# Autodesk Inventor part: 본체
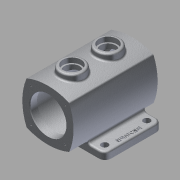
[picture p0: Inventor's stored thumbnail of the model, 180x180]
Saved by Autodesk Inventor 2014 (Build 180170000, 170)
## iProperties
Created: 2013-02
Part Number: 본체
Document SubType Name: Modeling
Designer: 한국산업디자인학원[gmhk.co.kr]
Density: 2.71 g/cm^3
Material: 알루미늄 6061
Mass: 1212.6 g
Surface Area: 1019.31 cm^2
Volume: 447.452 cm^3
Appearance: _시험_알루미늄 표면거칠기
Author: 한국산업디자인학원[gmhk.co.kr]
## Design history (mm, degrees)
sketch "스케치1"
  geometry: L1 (-65, 55)-(65, 55); L2 (65, 55)-(65, -40); L3 (65, -40)-(-65, -40); L4 (-65, -40)-(-65, 55); 2 further points
  constraints: 8 end point, 2 parallel, 1 horizontal, 1 midpoint, 1 perpendicular, 1 vertical alignment
  dimensions: "d0" = 130 distance of L2.end L3.end; "d1" = 95 distance of L1.end L2.end; "d47" = 40 distance from line of L3 point (0, 0)
extrude "돌출1" new body sketch "스케치1" distance "d2" = 12; taper "d3" = 0 deg
sketch "스케치2"
  geometry: L1 (-35.355, 85.355)-(35.355, 85.355); L2 (35.355, 85.355)-(35.355, 14.645); L3 (35.355, 14.645)-(-35.355, 14.645); L4 (-35.355, 14.645)-(-35.355, 85.355); L5 (35.355, 85.355)-(-35.355, 14.645); L6 (65, 0)-(-65, 0) reference; A1 r 91.05 centre (0, 1.45) between (35.355, 85.355) and (-35.355, 85.355); A2 r 91.05 centre (-48.55, 50) between (35.355, 14.645) and (35.355, 85.355); A3 r 91.05 centre (0, 98.55) between (-35.355, 14.645) and (35.355, 14.645); A4 r 91.05 centre (48.55, 50) between (-35.355, 85.355) and (-35.355, 14.645); 3 further points
  constraints: 10 end point, 8 point on circle, 4 centre point, 3 equal radius, 2 midpoint, 2 parallel, 2 perpendicular, 1 horizontal, 1 vertical alignment
  dimensions: "d4" = 50 distance from line of point (0, 50) L6; "d5" = 50 distance of L1.start point (0, 50); "d6" = 85 dimension on A2 A4
extrude "돌출2" join sketch "스케치2" stored distance "d7" = 140; taper "d8" = 0 deg
sketch "스케치3"
  geometry: L1 (28.27, 12)-(65, 12) reference; L2 (-65, 12)-(-28.27, 12) reference; A1 r 91.05 centre (0, 98.55) between (-35.355, 14.645) and (35.355, 14.645) reference; A2 r 91.05 centre (48.55, 50) between (-35.355, 85.355) and (-35.355, 14.645) reference; A3 r 91.05 centre (-48.55, 50) between (35.355, 14.645) and (35.355, 85.355) reference; A4 r 5 centre (-41.653, 17) between (-41.653, 12) and (-36.957, 18.718); A5 r 5 centre (41.653, 17) between (36.957, 18.718) and (41.653, 12); 1 further point
  constraints: 6 point on circle, 4 tangent, 2 centre point, 2 point on line, 1 equal radius
  dimensions: "d9" = 5 radius of A5
extrude "돌출3" join sketch "스케치3" stored distance "d10" = 120; taper "d11" = 0 deg
fillet "모깎기1" dims "d12" = 3
fillet "모깎기2" dims "d13" = 10
fillet "모깎기3" dims "d14" = 3
sketch "스케치4"
  geometry: L1 (-70, 84.185)-(-70, 85.839) reference; L2 (-70, 15.815)-(-70, 84.185) reference; L3 (-70, 14.161)-(-70, 15.815) reference; L4 (-70, 14.161)-(-70, 14.161) reference; L5 (-70, 15.815)-(-70, 14.161) reference; L6 (-70, 84.185)-(-70, 15.815) reference; L7 (-70, 85.839)-(-70, 84.185) reference; L8 (-70, 85.839)-(-70, 85.839) reference; L9 (70, 15.815)-(70, 14.161) reference; L10 (70, 84.185)-(70, 15.815) reference; L11 (70, 85.839)-(70, 84.185) reference; L12 (70, 85.839)-(70, 85.839) reference; L13 (70, 84.185)-(70, 85.839) reference; L14 (70, 15.815)-(70, 84.185) reference; L15 (70, 14.161)-(70, 15.815) reference; L16 (70, 14.161)-(70, 14.161) reference; L17 (-70, 50)-(70, 50); L18 (-70, 80)-(-58, 80); L19 (-58, 80)-(-58, 87.5); L20 (-58, 87.5)-(58, 87.5); L21 (58, 87.5)-(58, 80); L22 (58, 80)-(70, 80); 1 further point
  constraints: 12 end point, 2 collinear, 2 midpoint, 2 parallel, 2 perpendicular, 2 point on line
  dimensions: "d15" = 60 diameter of L18 L17; "d16" = 75 diameter of L20 L17; "d17" = 12 distance of L18.start L18.end; "d18" = 12 distance of L21.end L22.end
revolve "회전1" sketch "스케치4" stored, may be unused: angle "d19" = 90 deg
fillet "모깎기4" dims "d20" = 3
node "작업 평면2"
  node "작업 평면1"
sketch "스케치5"
  geometry: C1 r 20 at (0, 30); C2 r 20 at (0, -30); 1 further point
  constraints: 2 centre point, 2 vertical alignment
  dimensions: "d22" = 40 diameter of C1; "d23" = 40 diameter of C2; "d24" = 60 distance of C2.centre C1.centre; "d25" = 30 distance of point (0, 0) C1.centre (= 0.5 x d24)
extrude "돌출4" join sketch "스케치5" stored distance "d26" = 120; taper "d27" = 0 deg
fillet "모깎기5" dims "d28" = 3
hole "구멍1" diameter "d31" = 25; stored, may be unused: countersink angle "d35" = 90 deg, drill point angle "d37" = 118 deg; dims "d29" = 10, "d30" = 10, "d32" = 6, "d33" = 30, "d34" = 8, "d36" = 8
hole "구멍2" diameter "d40" = 25; stored, may be unused: countersink angle "d44" = 90 deg, drill point angle "d46" = 118 deg; dims "d38" = 10, "d39" = 10, "d41" = 6, "d42" = 30, "d43" = 8, "d45" = 8
sketch "스케치6"
  geometry: L1 (65, -30)-(65, 45) reference; 4 further points
  constraints: 1 midpoint, 1 vertical alignment
  dimensions: "d48" = 13 distance from line of point (52, 42.5) L1; "d49" = 70 distance of point (52, -27.5) point (52, 42.5); "d50" = 35 vertical distance of point (65, 7.5) point (52, 42.5) (= 0.5 x d49)
hole "구멍3" sketch "스케치6" at (52, -27.5), (52, 42.5) diameter "d51" = 11; stored, may be unused: countersink angle "d55" = 90 deg, drill point angle "d57" = 118 deg; dims "d52" = 6, "d53" = 30, "d54" = 8, "d56" = 8
sketch "스케치8"
  geometry: L1 (65, -30)-(65, 45) reference; 3 further points
  constraints: 1 horizontal alignment, 1 midpoint, 1 other
  dimensions: "d60" = 8 distance from line of point (57, 7.5) L1
feature "엠보싱2" sketch "스케치8" dims "d0" = 130, "d1" = 95, "d47" = 40, "d61" = 1, "d62" = 0
chamfer "모따기1" distance "d63" = 1; stored, may be unused: second distance "d64" = 2, angle "d65" = 45 deg
sketch "스케치9" dims "d9" = 5, "d75" = 40, "d76" = 360 deg
  geometry: L1 (0, 81)-(0, 50); L2 (0, 50)-(28.284, 78.284); 1 further point
  constraints: 4 end point, 1 vertical, 1 vertical alignment, 1 other
  dimensions: "d66" = 45 deg angle of L2 L1; "d67" = 40 distance of L2.end L1.end
hole "구멍4" sketch "스케치9" at (28.284, 78.284) diameter "d68" = 3.242; stored, may be unused: countersink angle "d72" = 90 deg, drill point angle "d74" = 118 deg; dims "d69" = 8, "d70" = 30, "d71" = 8, "d73" = 10
node "솔리드1"
mirror "대칭1"
pattern_circular "원형 패턴1" dims angle "d76" = 360 deg
mirror "대칭2"
node "투영된 루프1"
node "투영된 루프2"
